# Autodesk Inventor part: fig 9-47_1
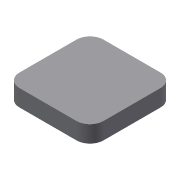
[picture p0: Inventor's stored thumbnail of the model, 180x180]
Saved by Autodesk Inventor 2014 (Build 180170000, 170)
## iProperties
Created: 2013-03
Part Number: fig 9-47_1
Material: Generic
Document SubType Name: Modeling
Designer: CADCIM
Density: 1 g/cm^3
Appearance: Default
Author: CADCIM
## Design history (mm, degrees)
sketch "Sketch1"
  geometry: L1 (-12.5, 12.5)-(12.5, 12.5); L2 (12.5, 12.5)-(12.5, -12.5); L3 (12.5, -12.5)-(-12.5, -12.5); L4 (-12.5, -12.5)-(-12.5, 12.5); 1 further point
  constraints: 8 end point, 2 parallel, 1 horizontal, 1 perpendicular
  dimensions: "d0" = 25 distance of L1.start L1.end; "d2" = 25 distance of L1.end L2.end
extrude "Extrusion1" new body sketch "Sketch1" distance "d3" = 5; taper "d4" = 0 deg
fillet "Fillet1" dims "d5" = 4
body "Solid1"
